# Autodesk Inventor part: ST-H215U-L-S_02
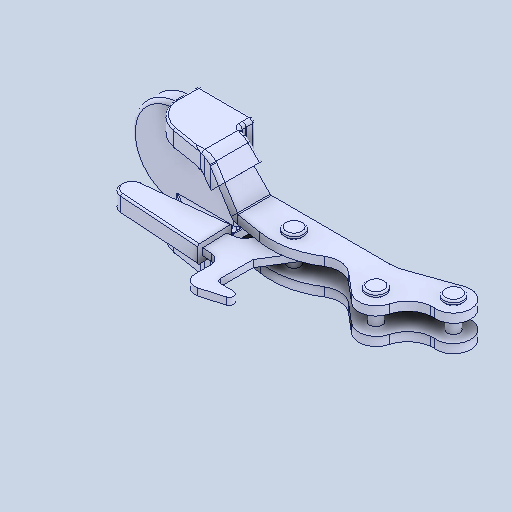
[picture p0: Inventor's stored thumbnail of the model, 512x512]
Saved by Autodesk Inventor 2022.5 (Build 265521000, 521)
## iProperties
Created: 2024-07
Part Number: ST-H215U-L-S_02
Material: 一般
Document SubType Name: Modeling
Designer: ImaoCorp
Density: 1 g/cm^3
Appearance: 既定
Author: ImaoCorp
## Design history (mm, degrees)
feature "ST-H215U-L-S_02"
node "ソリッド1"
